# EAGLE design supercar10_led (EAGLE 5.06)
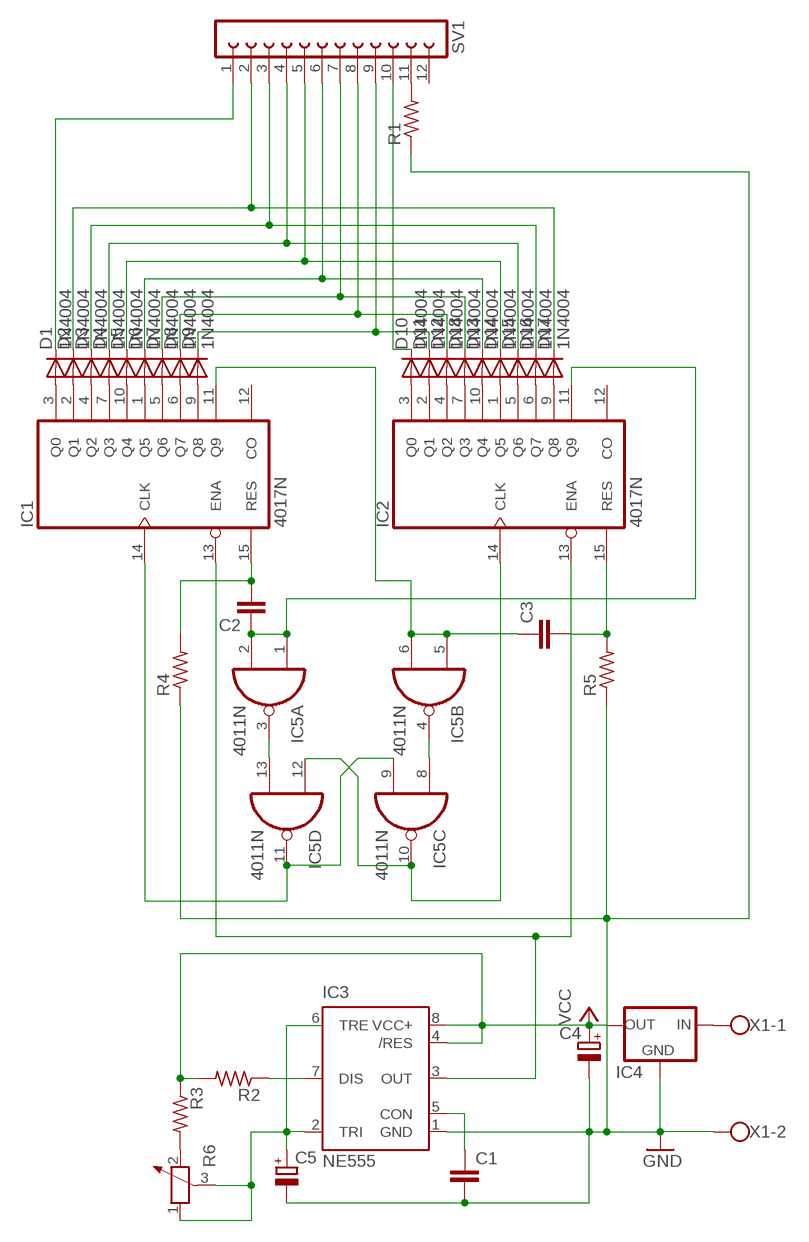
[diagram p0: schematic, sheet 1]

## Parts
C1  C-EU050-025X075  [C050-025X075]
C2  C-EU050-025X075  [C050-025X075]
C3  C-EU050-025X075  [C050-025X075]
C4  CPOL-EUE2,5-6E  [E2,5-6E]
C5  CPOL-EUE2,5-6E  [E2,5-6E]
D1  1N4004  [DO41-10]
D2  1N4004  [DO41-10]
D3  1N4004  [DO41-10]
D4  1N4004  [DO41-10]
D5  1N4004  [DO41-10]
D6  1N4004  [DO41-10]
D7  1N4004  [DO41-10]
D8  1N4004  [DO41-10]
D9  1N4004  [DO41-10]
D10  1N4004  [DO41-10]
D11  1N4004  [DO41-10]
D12  1N4004  [DO41-10]
D13  1N4004  [DO41-10]
D14  1N4004  [DO41-10]
D15  1N4004  [DO41-10]
D16  1N4004  [DO41-10]
D17  1N4004  [DO41-10]
D18  1N4004  [DO41-10]
IC1  4017N  [DIL16]
IC2  4017N  [DIL16]
IC3  NE555  [DIL-08]
IC4  78XXS  [78XXS]
IC5  4011N  [DIL14]
R1  R-US_0207/10  [0207/10]
R2  R-US_0207/10  [0207/10]
R3  R-US_0207/10  [0207/10]
R4  R-US_0207/10  [0207/10]
R5  R-US_0207/10  [0207/10]
R6  POTENTIOMETER_PT-10  [PT-10]
SV1  FE12-1  [FE12]
X1  W237-102  [W237-102]

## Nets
GND: C1.2 C4.- C5.- IC3.1(GND) IC4.GND R1.1 R4.1 R5.1 X1.2
N$1: D1.A IC1.3(Q0)
N$2: D2.A IC1.2(Q1)
N$3: D3.A IC1.4(Q2)
N$4: D4.A IC1.7(Q3)
N$5: D5.A IC1.10(Q4)
N$6: D6.A IC1.1(Q5)
N$7: D7.A IC1.5(Q6)
N$8: D8.A IC1.6(Q7)
N$9: D9.A IC1.9(Q8)
N$10: D10.A IC2.3(Q0)
N$11: D11.A IC2.2(Q1)
N$12: D12.A IC2.4(Q2)
N$13: D18.A IC2.7(Q3)
N$14: D13.A IC2.10(Q4)
N$15: D14.A IC2.1(Q5)
N$16: D15.A IC2.5(Q6)
N$17: D16.A IC2.6(Q7)
N$18: D17.A IC2.9(Q8)
N$19: D9.C D11.C SV1.9
N$20: D8.C D12.C SV1.8
N$21: D7.C D18.C SV1.7
N$22: D6.C D13.C SV1.6
N$23: D5.C D14.C SV1.5
N$24: D4.C D15.C SV1.4
N$25: D3.C D16.C SV1.3
N$26: D2.C D17.C SV1.2
N$27: D1.C SV1.1
N$28: D10.C SV1.10
N$29: R1.2 SV1.11
N$32: C2.1 IC2.11(Q9) IC5.1(A:I0) IC5.2(A:I1)
N$33: IC3.7(DIS) R2.1
N$34: C5.+ IC3.2(TRI) R6.1 R6.3
N$35: C3.1 IC1.11(Q9) IC5.5(B:I0) IC5.6(B:I1)
N$36: C1.1 IC3.5(CON)
N$37: IC4.IN X1.1
N$38: R3.2 R6.2
N$39: IC2.14(CLK) IC5.10(C:O) IC5.12(D:I0)
N$40: IC1.14(CLK) IC5.9(C:I1) IC5.11(D:O)
N$41: IC5.4(B:O) IC5.8(C:I0)
N$43: C2.2 IC1.15(RES) R4.2
N$44: IC5.3(A:O) IC5.13(D:I1)
N$45: C3.2 IC2.15(RES) R5.2
N$46: IC1.13(ENA) IC2.13(ENA) IC3.3(OUT)
VCC: C4.+ IC3.4(/RES) IC3.8(VCC+) IC4.OUT R2.2 R3.1
Unconnected: IC1.12(CO) IC2.12(CO) IC3.6(TRE) SV1.12

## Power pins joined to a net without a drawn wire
VDD: IC1.16(VDD) IC2.16(VDD) IC5.14(P:VDD)
VSS: IC1.8(VSS) IC2.8(VSS) IC5.7(P:VSS)

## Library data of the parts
C1-C3 = resistor:C-EU: CAPACITOR, European symbol
C4 C5 = resistor:CPOL-EU: POLARIZED CAPACITOR, European symbol
D1-D18 = diode:1N4004: DIODE
IC1 IC2 = 40xx:4017: COUNTER/DIVIDER
IC3 = st-microelectronics:NE555: General purpose bipolar Timer
IC4 = v-reg:78XXS: VOLTAGE REGULATOR
IC5 = 40xx:4011: Quad 2-input NAND
R1-R5 = resistor:R-US_: RESISTOR, American symbol
R6 = rcl:POTENTIOMETER_: Potentiometer
SV1 = con-lsta:FE12-1: FEMALE HEADER
X1 = con-wago-500:W237-102: WAGO SCREW CLAMP

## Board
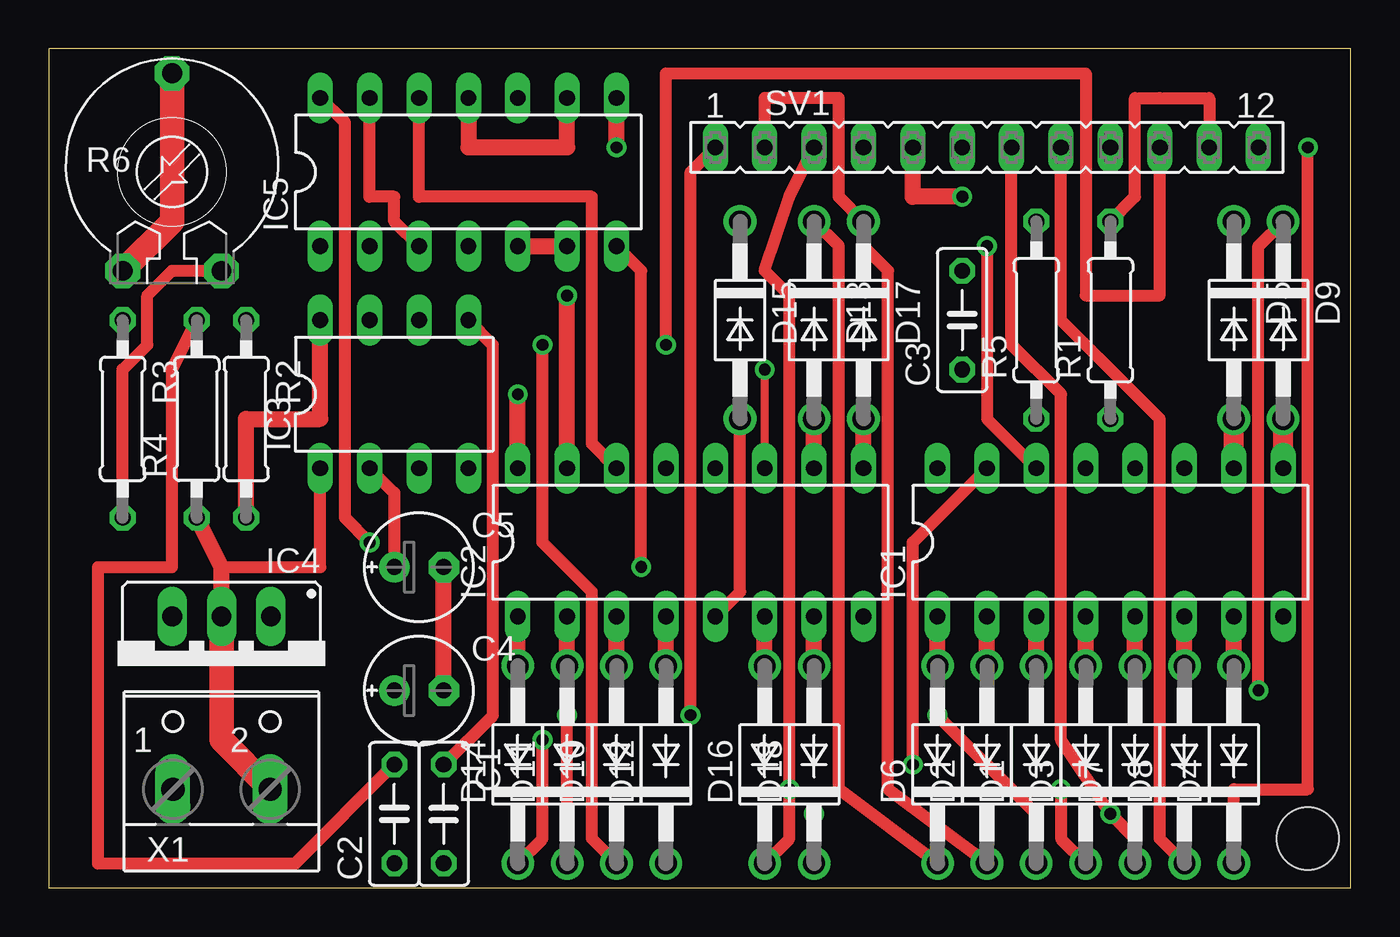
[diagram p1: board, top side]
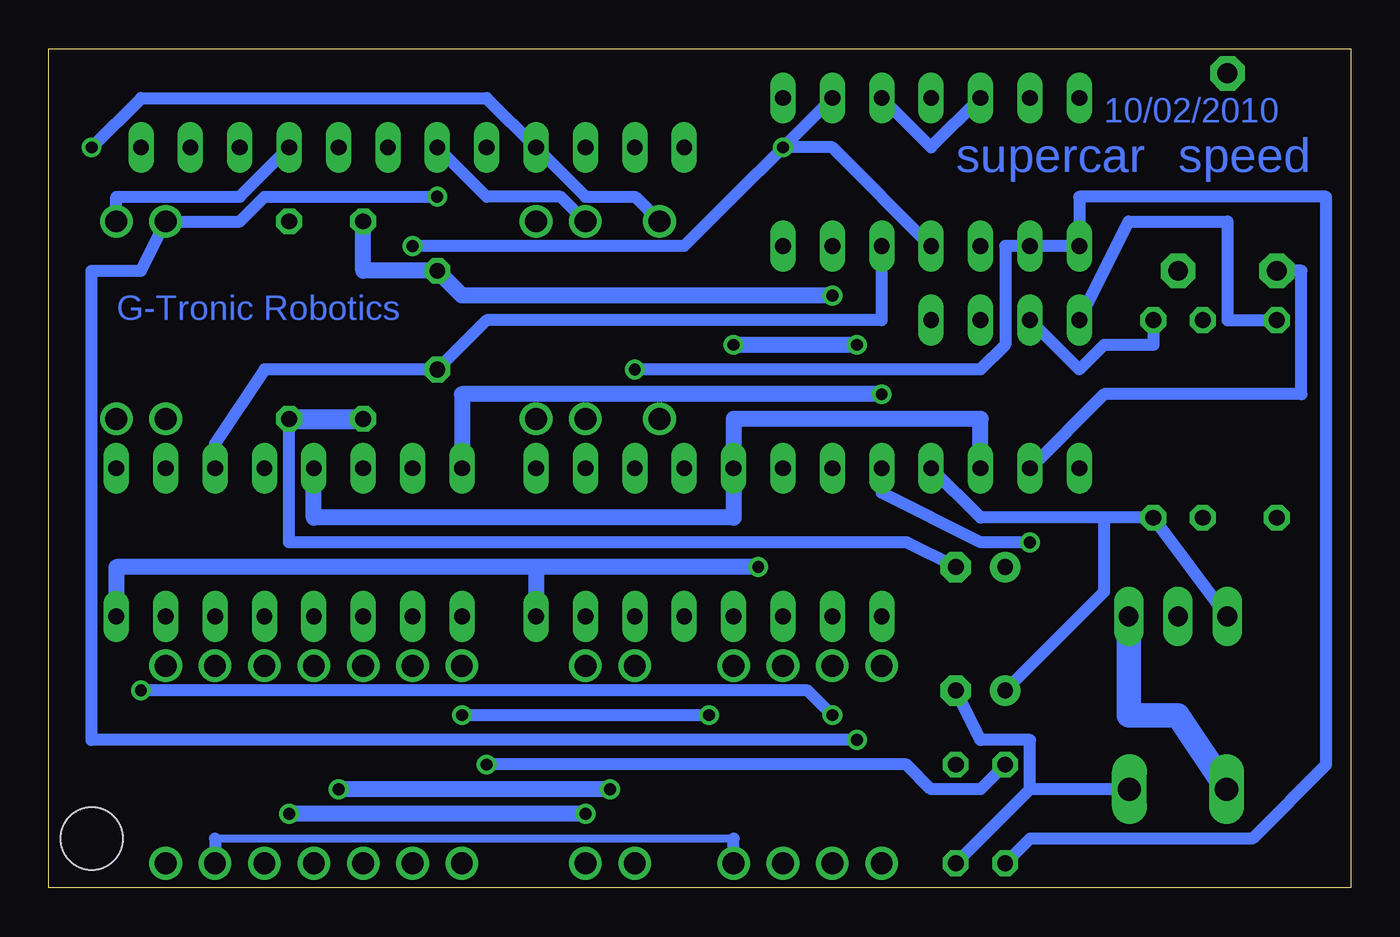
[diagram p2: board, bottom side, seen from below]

Size 66.98 x 43.17 mm. Coordinates in mm from the lower left corner, seen from the top.
Outline: 0,0 66.98,0 66.98,43.17 0,43.17 0,0
Copper layers (1*16): Top 0.035mm / dielectric 1.5mm / Bottom 0.035mm
Design rules "default": minimum track width 10mil, minimum drill 24mil, track to track 8mil, track to pad 8mil, pad to pad 8mil, via to via 8mil, smd to smd 8mil, copper to edge 40mil, drill to drill 8mil, minimum pad ring 10mil, minimum via ring 8mil, stop-mask expansion 4mil, vias tented up to drill 0mil, thermal gap 10mil
Holes 3.2 mm at 64.77,2.54

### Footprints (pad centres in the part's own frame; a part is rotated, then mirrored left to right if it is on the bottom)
C050-025X075 = drill 0.813 octagon: 1 -2.54,0; 2 2.54,0
E2,5-6E = drill 0.813 pad 1.575 round: + -1.27,0 | drill 0.813 pad 1.575 octagon: - 1.27,0
DO41-10 = drill 1.118 round: A 5.08,0; C -5.08,0
DIL16 = drill 0.813 long: 1 -8.89,-3.81; 2 -6.35,-3.81; 3 -3.81,-3.81; 4 -1.27,-3.81; 5 1.27,-3.81; 6 3.81,-3.81; 7 6.35,-3.81; 8 8.89,-3.81; 9 8.89,3.81; 10 6.35,3.81; 11 3.81,3.81; 12 1.27,3.81; 13 -1.27,3.81; 14 -3.81,3.81; 15 -6.35,3.81; 16 -8.89,3.81
DIL-08 = drill 0.813 long: 1 -3.81,-3.81; 2 -1.27,-3.81; 3 1.27,-3.81; 4 3.81,-3.81; 5 3.81,3.81; 6 1.27,3.81; 7 -1.27,3.81; 8 -3.81,3.81
78XXS = drill 1.016 long: GND 0,-2.54; IN -2.54,-2.54; OUT 2.54,-2.54
DIL14 = drill 0.813 long: 1 -7.62,-3.81; 2 -5.08,-3.81; 3 -2.54,-3.81; 4 0,-3.81; 5 2.54,-3.81; 6 5.08,-3.81; 7 7.62,-3.81; 8 7.62,3.81; 9 5.08,3.81; 10 2.54,3.81; 11 0,3.81; 12 -2.54,3.81; 13 -5.08,3.81; 14 -7.62,3.81
0207/10 = drill 0.813 octagon: 1 -5.08,0; 2 5.08,0
PT-10 = drill 1.016 pad 1.778 octagon: 1 -2.54,-5.08; 2 2.54,-5.08; 3 0,5.08
FE12 = drill 0.813 long: 1 -13.97,0; 2 -11.43,0; 3 -8.89,0; 4 -6.35,0; 5 -3.81,0; 6 -1.27,0; 7 1.27,0; 8 3.81,0; 9 6.35,0; 10 8.89,0; 11 11.43,0; 12 13.97,0
W237-102 = drill 1.194 long: 1 -2.5,-1.27; 2 2.5,-1.27

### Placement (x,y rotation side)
C1  20.32,3.81 270 top
C2  17.78,3.81 90 top
C3  46.99,29.21 90 top
C4  19.05,10.16 0 top
C5  19.05,16.51 0 top
D1  50.8,6.35 90 top
D2  48.26,6.35 90 top
D3  53.34,6.35 90 top
D4  60.96,6.35 90 top
D5  60.96,29.21 270 top
D6  45.72,6.35 90 top
D7  55.88,6.35 90 top
D8  58.42,6.35 90 top
D9  63.5,29.21 270 top
D10  29.21,6.35 90 top
D11  26.67,6.35 90 top
D12  31.75,6.35 90 top
D13  39.37,29.21 270 top
D14  24.13,6.35 90 top
D15  35.56,29.21 270 top
D16  36.83,6.35 90 top
D17  41.91,29.21 270 top
D18  39.37,6.35 90 top
IC1  54.61,17.78 0 top
IC2  33.02,17.78 0 top
IC3  17.78,25.4 0 top
IC4  8.89,11.43 180 top
IC5  21.59,36.83 0 top
R1  54.61,29.21 90 top
R2  10.16,24.13 270 top
R3  3.81,24.13 270 top
R4  7.62,24.13 90 top
R5  50.8,29.21 90 top
R6  6.35,36.83 0 top
SV1  48.26,38.1 0 top
X1  8.89,6.35 0 top

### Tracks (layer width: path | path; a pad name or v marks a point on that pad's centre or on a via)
GND
  Top 0.254: X1.2 11.43,5.08
  Top 0.61: 8.89,16.51 13.97,16.51 IC3.1
  Top 0.813: R4.1 8.89,16.51 IC4.GND | C4.- C5.-
  Top 1.27: 11.43,5.08 8.89,7.62 IC4.GND
  Bottom 0.61: 16.51,5.08 C1.2 | X1.2 16.51,5.08 | R1.1 54.61,17.78 22.86,17.78 C5.- | 16.51,5.08 16.51,7.62 19.05,7.62 C4.-
  Bottom 1.016: R1.1 R5.1
N$1
  Top 0.813: D1.A IC1.3
N$2
  Top 0.813: D2.A IC1.2
N$3
  Top 0.813: D3.A IC1.4
N$4
  Top 0.813: D4.A IC1.7
N$5
  Top 1.016: IC1.10 D5.A
N$6
  Top 0.813: D6.A IC1.1
N$7
  Top 0.813: D7.A IC1.5
N$8
  Top 0.813: D8.A IC1.6
N$9
  Top 1.016: IC1.9 D9.A
N$10
  Top 0.813: D10.A IC2.3
N$11
  Top 0.813: D11.A IC2.2
N$12
  Top 0.813: D12.A IC2.4
N$13
  Top 0.813: D18.A IC2.7
N$14
  Top 0.813: IC2.10 D13.A
N$15
  Top 0.813: D14.A IC2.1
N$16
  Top 0.61: IC2.5 35.56,15.24 D15.A
N$17
  Top 0.813: D16.A IC2.6
N$18
  Top 0.813: IC2.9 D17.A
N$19  (via drill 0.61)
  Top 0.61: D11.C v26.67,8.89 | v62.23,10.16 62.23,33.02 D9.C
  Bottom 0.61: SV1.9 57.15,35.56 63.5,35.56 D9.C | v26.67,8.89 27.94,10.16 v62.23,10.16
N$20
  Top 0.61: SV1.8 52.07,29.21 57.15,24.13 57.15,2.54 D8.C
  Bottom 0.406: 31.75,2.54 58.42,2.54
  Bottom 0.61: D12.C 31.75,2.54 | 58.42,2.54 D8.C
N$21  (via drill 0.61)
  Top 0.61: SV1.7 49.53,27.94 52.07,25.4 52.07,7.62 v54.61,3.81 55.88,2.54 D7.C | D18.C v39.37,3.81
  Bottom 0.813: v39.37,3.81 v54.61,3.81
N$22
  Top 0.61: D6.C 40.64,5.08 40.64,33.02 D13.C
  Bottom 0.61: SV1.6 44.45,35.56 40.64,35.56 D13.C
N$23  (via drill 0.61)
  Top 0.61: D14.C 25.4,2.54 v25.4,7.62
  Top 0.813: v46.99,35.56 44.45,35.56 SV1.5
  Bottom 0.61: v46.99,35.56 55.88,35.56 57.15,34.29 D5.C 62.23,31.75 64.77,31.75 64.77,7.62 v25.4,7.62
N$24  (via drill 0.61)
  Top 0.61: D4.C 60.96,5.08 64.77,5.08 v64.77,38.1
  Bottom 0.61: D15.C 36.83,35.56 39.37,35.56 SV1.4 44.45,40.64 62.23,40.64 v64.77,38.1
N$25  (via drill 0.61)
  Top 0.61: SV1.3 38.1,35.56 36.83,31.75 38.1,30.48 v38.1,5.08 38.1,2.54 D16.C | D3.C 52.07,2.54 v52.07,5.08
  Bottom 0.813: v38.1,5.08 v52.07,5.08
N$26
  Top 0.61: SV1.2 36.83,40.64 40.64,40.64 40.64,35.56 D17.C 41.91,33.02 43.18,31.75 43.18,5.08 D2.C
N$27  (via drill 0.61)
  Top 0.61: SV1.1 33.02,36.83 v33.02,8.89 | v45.72,8.89 50.8,3.81 D1.C
  Bottom 0.61: v33.02,8.89 v45.72,8.89
N$28  (via drill 0.61)
  Top 0.61: SV1.10 57.15,30.48 53.34,30.48 53.34,41.91 31.75,41.91 v31.75,27.94 | v25.4,27.94 25.4,17.78 27.94,15.24 27.94,2.54 D10.C
  Bottom 0.813: v25.4,27.94 v31.75,27.94
N$29
  Top 0.61: R1.2 55.88,35.56 55.88,40.64 57.15,40.64 59.69,40.64 SV1.11
N$32  (via drill 0.61)
  Top 0.406: v36.83,26.67 IC2.11
  Bottom 0.61: C2.1 16.51,2.54 5.08,2.54 1.27,6.35 1.27,35.56 13.97,35.56 IC5.1 IC5.2 17.78,33.02 17.78,27.94 19.05,26.67 v36.83,26.67
N$33
  Bottom 0.61: R2.1 10.16,27.94 12.7,27.94 13.97,26.67 IC3.7
N$34
  Top 0.61: IC3.2 17.78,20.32 C5.+
  Top 1.27: R6.1 6.35,34.29 R6.3
  Bottom 0.61: IC3.2 12.7,25.4 2.54,25.4 2.54,31.75 R6.1
N$35
  Top 0.813: IC5.5 IC5.6
  Bottom 0.61: IC1.11 58.42,22.86 55.88,26.67 C3.1 44.45,29.21 24.13,29.21 IC5.5
N$36
  Top 0.61: C1.1 22.86,8.89 22.86,27.94 IC3.5
N$37
  Bottom 0.254: X1.1 6.35,5.08
  Bottom 1.27: IC4.IN 11.43,8.89 8.89,8.89 6.35,5.08
N$38
  Top 0.61: R3.2 3.81,26.67 5.08,27.94 5.08,30.48 6.35,31.75 R6.2
N$39
  Top 0.61: IC2.14 27.94,22.86 27.94,35.56 19.05,35.56 IC5.12
  Bottom 0.61: IC5.12 21.59,38.1 IC5.10
N$40  (via drill 0.61)
  Top 0.61: IC1.14 48.26,24.13 v48.26,33.02
  Top 0.813: IC5.11 21.59,38.1 26.67,38.1 IC5.9
  Bottom 0.61: v48.26,33.02 34.29,33.02 IC5.9
N$41  (via drill 0.61)
  Top 0.813: v29.21,38.1 IC5.8
  Bottom 0.61: IC5.4 26.67,38.1 v29.21,38.1
N$43  (via drill 0.61)
  Top 0.61: C2.2 12.7,1.27 2.54,1.27 2.54,16.51 6.35,16.51 6.35,26.67 R4.2 | IC1.15 44.45,17.78 v44.45,6.35
  Bottom 0.61: v44.45,6.35 22.86,6.35 21.59,5.08 19.05,5.08 C2.2
N$44
  Top 0.61: IC5.3 17.78,34.29 17.78,35.56 16.51,35.56 IC5.13
N$45  (via drill 0.61)
  Top 0.813: IC2.15 v26.67,30.48
  Bottom 0.813: v26.67,30.48 45.72,30.48 C3.2 50.8,31.75 R5.2
N$46
  Bottom 0.813: IC3.3 19.05,24.13 31.75,24.13 IC2.13 31.75,19.05 53.34,19.05 IC1.13
VCC
  Top 0.813: R2.2 10.16,24.13 13.97,24.13 IC3.8
  Bottom 0.61: IC3.4 19.05,19.05 12.7,19.05 | 12.7,19.05 R2.2 IC4.OUT | R3.1 6.35,29.21 6.35,30.48 6.35,34.29 11.43,34.29 IC3.8 | C4.+ 12.7,15.24 12.7,19.05
VDD  (via drill 0.61)
  Top 0.61: v16.51,17.78 15.24,19.05 15.24,39.37 IC5.14
  Top 0.813: IC2.16 v24.13,25.4
  Bottom 0.61: IC2.16 24.13,20.32 19.05,17.78 v16.51,17.78
  Bottom 0.813: IC1.16 45.72,25.4 v24.13,25.4
VSS  (via drill 0.61)
  Top 0.61: IC5.7 30.48,31.75 v30.48,16.51
  Bottom 0.813: 41.91,16.51 IC2.8 | 41.91,16.51 63.5,16.51 IC1.8 | v30.48,16.51 41.91,16.51

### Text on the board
Bottom: 10/02/2010 | speed | supercar | G-Tronic Robotics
